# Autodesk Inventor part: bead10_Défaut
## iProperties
Shininess: 64.0
Length Units: 11269
Angle Units: 11279
Time Units: 11290
Mass Units: 11283
Length Display Precision: 3
Angle Display Precision: 2
Compacted: True
Part Number: bead10_Défaut
Document SubType Name: Modeling
Created: 2006-01
Material: Par défaut
Designer: Fricot
Density: 0.0
Volumn: 0.0
Area: 0.0
PropertySet Name: Model Information
Control State: 0
Master: False
Checked Out: False
Author: Fricot
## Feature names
1. Base1
